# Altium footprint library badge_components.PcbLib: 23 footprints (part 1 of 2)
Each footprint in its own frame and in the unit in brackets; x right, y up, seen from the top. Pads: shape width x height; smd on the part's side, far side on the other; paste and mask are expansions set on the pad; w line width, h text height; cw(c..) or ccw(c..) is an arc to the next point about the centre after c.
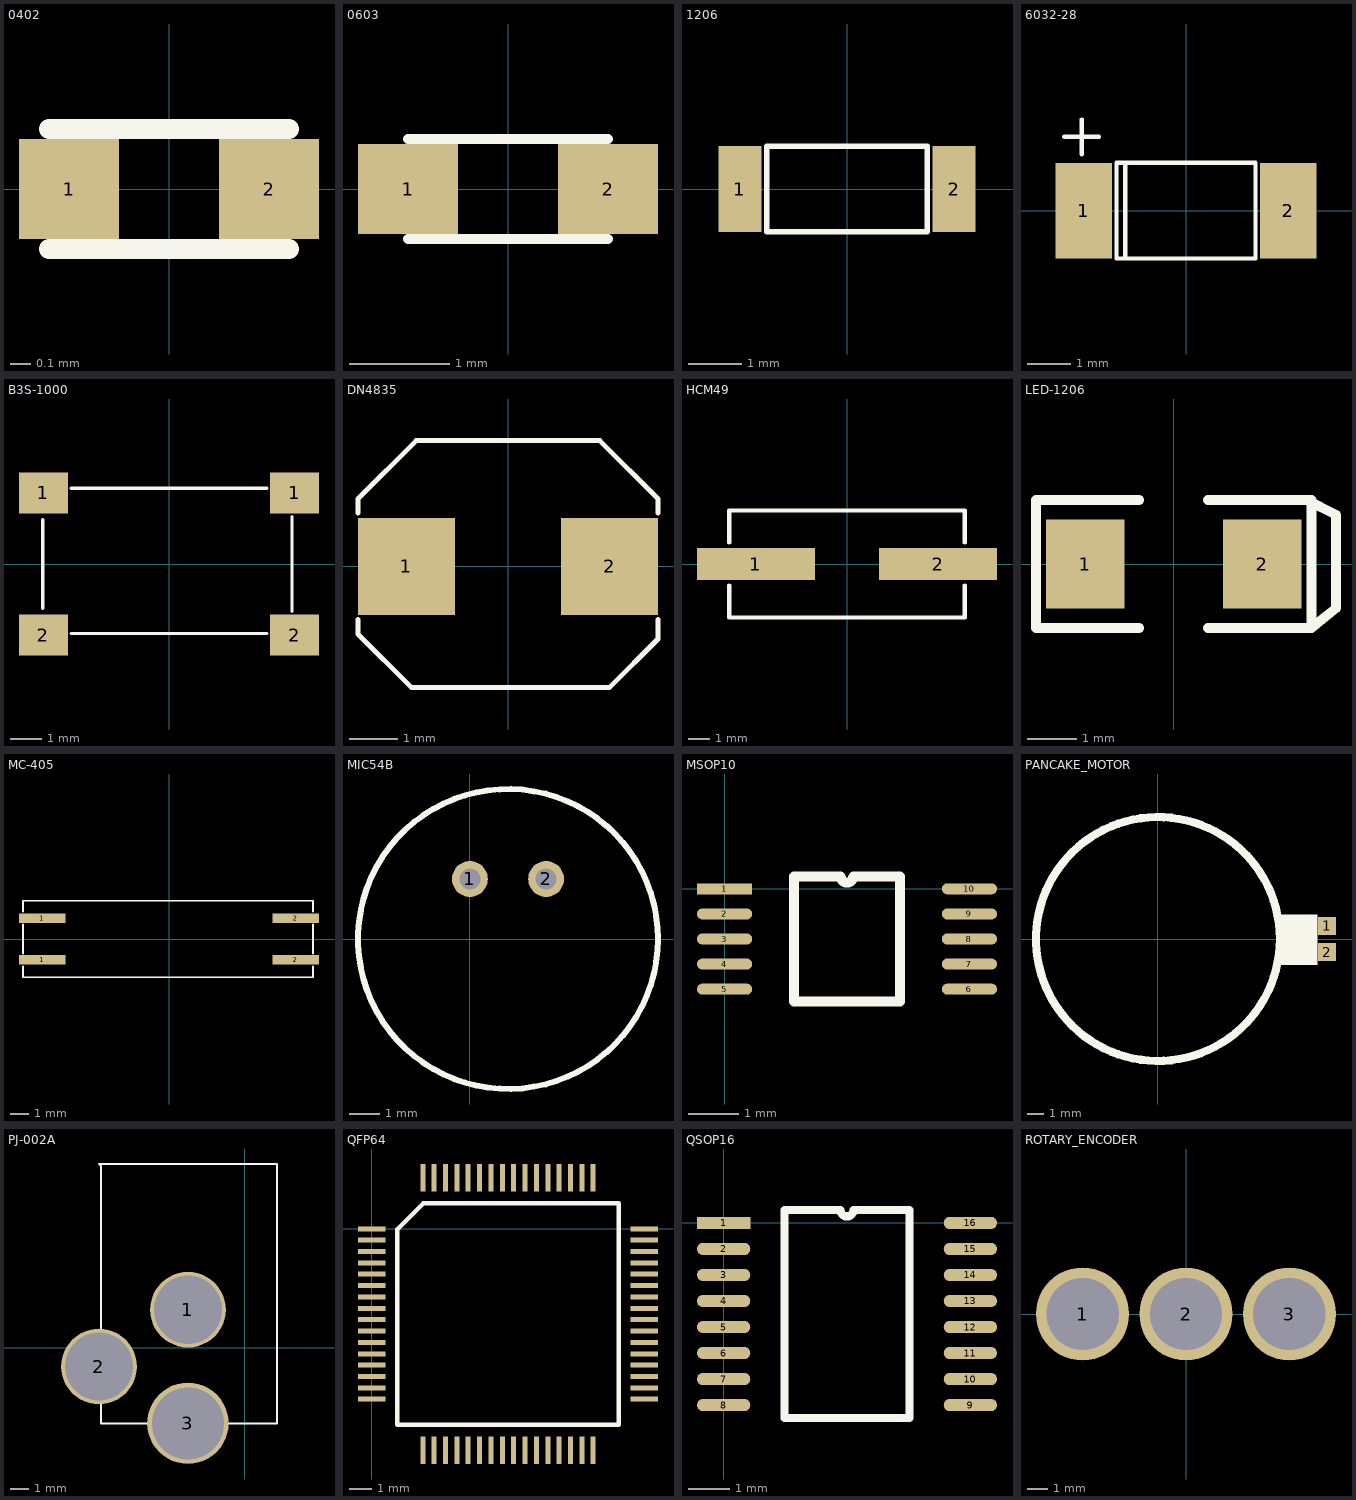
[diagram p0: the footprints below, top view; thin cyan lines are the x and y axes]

## 0402 [mm]
height 0.5
pads (2):
  rect 0.5x0.5 smd: 1(-0.5,0) 2(0.5,0)
Top Overlay:
  lines w0.1: -0.6,-0.3 0.6,-0.3 ; -0.6,0.3 0.6,0.3

## 0603 [mm]
height 1
pads (2):
  rect 1x0.9 smd: 1(-1,0) 2(1,0)
Top Overlay:
  lines w0.1: -1,-0.5 1,-0.5 ; -1,0.5 1,0.5

## 1206 [mm]
height 1.6
pads (2):
  rect 0.8x1.6 smd: 1(-2,0) 2(2,0)
Top Overlay:
  lines w0.1: -1.5,-0.8 1.5,-0.8 1.5,0.8 -1.5,0.8 -1.5,-0.8

## 6032-28 [mm]
height 2.5
pads (2):
  rect 1.3x2.2 smd: 1(-2.35,0) 2(2.35,0)
Top Overlay:
  lines w0.1: -2.8,1.7 -2,1.7 ; -2.4,1.3 -2.4,2.1 ; -1.4,-1.1 -1.4,1.1 ; -1.6,-1.1 1.6,-1.1 1.6,1.1 -1.6,1.1 -1.6,-1.1

## B3S-1000 [mm]
height 4.3
pads (4):
  rect 1.55x1.3 smd: 1(-3.975,2.25) 1(3.975,2.25) 2(-3.975,-2.25) 2(3.975,-2.25)
Top Overlay:
  lines w0.1: -4,-1.4 -4,1.4 ; -3.1,-2.2 3.1,-2.2 ; -3.1,2.4 3.1,2.4 ; 3.9,-1.5 3.9,1.5

## DN4835 [mm]
height 3.5
pads (2):
  rect 2x2 smd: 1(-2.1,0) 2(2.1,0)
Top Overlay:
  lines w0.1: -3.1,-1.1 -3.1,-1.4 -2,-2.5 2.1,-2.5 3.1,-1.5 3.1,-1.1 ; -3.1,1.1 -3.1,1.4 -1.9,2.6 1.9,2.6 3.1,1.4 3.1,1.1 ; 3.1,-1.1 3.1,-1.1

## HCM49 [mm]
height 4.3
pads (2):
  rect 5.5x1.5 smd: 1(-4.25,0) 2(4.25,0)
Top Overlay:
  lines w0.2: -5.5,-1 -5.5,-2.5 5.5,-2.5 5.5,-1 ; -5.5,1 -5.5,2.5 5.5,2.5 5.5,1

## LED-1206 [mm]
height 1.6
pads (2):
  rect 1.6x1.8 smd: 1(-1.8,0) 2(1.8,0)
Top Overlay:
  lines w0.2: -0.7,-1.3 -2.8,-1.3 -2.8,1.3 -0.7,1.3 ; 0.7,-1.3 2.8,-1.3 ; 0.7,1.3 2.8,1.3 ; 2.8,-1.3 3.3,-0.9 3.3,1 2.7,1.3 2.8,1.3 ; 2.8,-1.3 2.8,1.3

## MC-405 [mm]
height 3.6
pads (4):
  rect 2.54x0.51 smd: 1(-6.957,-1.145) 1(-6.957,1.145) 2(6.957,-1.145) 2(6.957,1.145)
Top Overlay:
  lines w0.1: -8,-1.5 -8,-2.1 7.9,-2.1 7.9,-1.5 ; -8,-0.8 -8,0.8 ; -8,1.5 -8,2.1 7.9,2.1 7.9,1.5 ; 7.9,-0.8 7.9,0.8

## MIC54B [mm]
pads (2):
  round 1.2 hole 0.7: 1(0,2) 2(2.54,2)
Top Overlay:
  circle w0.2: c1.27,0 r5

## MSOP10 [mm]
height 1.07
pads (10):
  rect 1.1x0.22 smd: 1(0,0)
  oval 1.1x0.22 smd: 2(0,-0.5) 3(0,-1) 4(0,-1.5) 5(0,-2) 6(4.88,-2) 7(4.88,-1.5) 8(4.88,-1) 9(4.88,-0.5) 10(4.88,0)
Top Overlay:
  lines w0.2: 1.385,-2.25 3.495,-2.25 3.495,0.25 2.565,0.25 cw(c2.44,0.25) 2.315,0.25 1.385,0.25 1.385,-2.25

## PANCAKE_MOTOR [mm]
height 3.5
pads (2):
  rect 1.1x1.1 smd: 1(10.4,0.8) 2(10.4,-0.8)
Top Overlay:
  circle w0.5: c0,0 r7.5
  rectangle: 7.3,-1.6 9.8,1.5

## PJ-002A [mm]
height 11
pads (3):
  round 4 hole 3.6: 1(-3,2) 2(-7.7,-1)
  round 4.3 hole 3.8: 3(-3,-4)
Top Overlay:
  lines w0.1: -7.7,9.7 1.7,9.7 1.7,-4 -7.6,-4 -7.6,9.6 -7.7,9.7

## QFP64 [mm]
height 1.6
pads (64):
  rect 1.2x0.22 smd: 1(0,0) 2(0,-0.5) 3(0,-1) 4(0,-1.5) 5(0,-2) 6(0,-2.5) 7(0,-3) 8(0,-3.5) 9(0,-4) 10(0,-4.5) 11(0,-5) 12(0,-5.5) 13(0,-6) 14(0,-6.5) 15(0,-7) 16(0,-7.5) 33(12,-7.5) 34(12,-7) 35(12,-6.5) 36(12,-6) 37(12,-5.5) 38(12,-5) 39(12,-4.5) 40(12,-4) 41(12,-3.5) 42(12,-3) 43(12,-2.5) 44(12,-2) 45(12,-1.5) 46(12,-1) 47(12,-0.5) 48(12,0)
  rect 0.22x1.2 smd: 17(2.25,-9.75) 18(2.75,-9.75) 19(3.25,-9.75) 20(3.75,-9.75) 21(4.25,-9.75) 22(4.75,-9.75) 23(5.25,-9.75) 24(5.75,-9.75) 25(6.25,-9.75) 26(6.75,-9.75) 27(7.25,-9.75) 28(7.75,-9.75) 29(8.25,-9.75) 30(8.75,-9.75) 31(9.25,-9.75) 32(9.75,-9.75) 49(9.75,2.25) 50(9.25,2.25) 51(8.75,2.25) 52(8.25,2.25) 53(7.75,2.25) 54(7.25,2.25) 55(6.75,2.25) 56(6.25,2.25) 57(5.75,2.25) 58(5.25,2.25) 59(4.75,2.25) 60(4.25,2.25) 61(3.75,2.25) 62(3.25,2.25) 63(2.75,2.25) 64(2.25,2.25)
Top Overlay:
  lines w0.2: 1.135,-8.615 1.135,-0.02 2.27,1.115 10.865,1.115 10.865,-8.615 1.135,-8.615

## QSOP16 [mm]
height 1.73
pads (16):
  rect 1.3x0.3 smd: 1(0,0)
  oval 1.3x0.3 smd: 2(0,-0.635) 3(0,-1.27) 4(0,-1.905) 5(0,-2.54) 6(0,-3.175) 7(0,-3.81) 8(0,-4.445) 9(6.02,-4.445) 10(6.02,-3.81) 11(6.02,-3.175) 12(6.02,-2.54) 13(6.02,-1.905) 14(6.02,-1.27) 15(6.02,-0.635) 16(6.02,0)
Top Overlay:
  lines w0.2: 1.485,-4.763 1.485,0.318 2.851,0.318 ccw(c3.01,0.318) 3.169,0.317 4.535,0.318 4.535,-4.763 1.485,-4.763

## ROTARY_ENCODER [mm]
pads (3):
  round 4.5 hole 3.5: 1(-5,0) 2(0,0) 3(5,0)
